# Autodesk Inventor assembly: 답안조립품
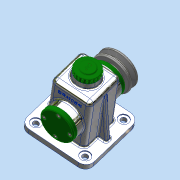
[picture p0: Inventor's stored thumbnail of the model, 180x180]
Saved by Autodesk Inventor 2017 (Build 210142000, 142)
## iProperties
Part Number: 답안조립품
Material: 일반
Document SubType Name: Assembly
Designer: MRC
Author: MRC
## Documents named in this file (14)
- C:\Users\MRC\Desktop\700907V1001\답안조립품.iam
- C:\Users\MRC\Desktop\700907V1001\본체.ipt
- C:\Users\MRC\Desktop\700907V1001\V-벨트풀리.ipt
- C:\Users\MRC\Desktop\700907V1001\뒤커버.ipt
- C:\Users\MRC\Desktop\700907V1001\멈춤링 15 x 1.ipt
- C:\Users\MRC\Desktop\700907V1001\베어링 15 x 35 x 11.ipt
- C:\Users\MRC\Desktop\700907V1001\볼트 M4 x 10.ipt
- C:\Users\MRC\Desktop\700907V1001\볼트 M6 x 12.ipt
- C:\Users\MRC\Desktop\700907V1001\상부캡.ipt
- C:\Users\MRC\Desktop\700907V1001\앞커버.ipt
- C:\Users\MRC\Desktop\700907V1001\오일실 15 25 7.ipt
- C:\Users\MRC\Desktop\700907V1001\와셔.ipt
- C:\Users\MRC\Desktop\700907V1001\축.ipt
- C:\Users\MRC\Desktop\700907V1001\키 5 x 5 x 14.ipt
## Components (1 placed, 1 different names)
1. V-벨트풀리:1
